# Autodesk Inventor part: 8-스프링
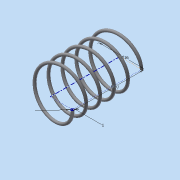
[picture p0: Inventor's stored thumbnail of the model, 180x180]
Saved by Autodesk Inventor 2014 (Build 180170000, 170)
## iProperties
Created: 2015-06
Part Number: 8-스프링
Material: 강철, 연강
Document SubType Name: Modeling
Designer: MYHOME
Density: 7.86 g/cm^3
Appearance: 강철
Mass: 1.53479 g
Surface Area: 7.89194 cm^2
Volume: 0.195266 cm^3
Author: MYHOME
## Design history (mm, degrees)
sketch "스케치1"
  geometry: L1 (0, 0)-(8, 0); L2 (8, 0)-(8, 21.5); L3 (8, 21.5)-(0, 21.5); L4 (0, 21.5)-(0, 0); C1 r 0.5 at (8, 0)
  constraints: 8 end point, 2 parallel, 1 centre point, 1 coincident, 1 horizontal, 1 perpendicular
  dimensions: "d0" = 1 diameter of C1; "d1" = 16 diameter of L2 L4; "d2" = 21.5 distance of L1.end L2.end (derived)
feature "코일1" sketch "스케치1" pitch "d3" = 10; turns "d5" = 5; dims "d4" = 21.5 (= d2), "d6" = 0, angle "d7" = 90 deg, angle "d8" = 90 deg, "d9" = 0, "d10" = 0
sketch "스케치2"
  geometry: L1 (-8.5, 0)-(-7.5, 0) reference; 1 further point
  constraints: 1 horizontal alignment
extrude "돌출1" cut sketch "스케치2" stored distance "d11" = 10; taper "d12" = 0 deg
node "작업 평면1"
sketch "스케치3"
  geometry: L1 (-7.5, 0)-(-8.5, 0) reference; 1 further point
  constraints: 1 horizontal alignment
extrude "돌출2" cut sketch "스케치3" stored distance "d14" = 10; taper "d15" = 0 deg
node "솔리드1"
node "절단 모서리 투영1"
node "절단 모서리 투영2"
other parameters: "d13" = 21.5 (= d2)
